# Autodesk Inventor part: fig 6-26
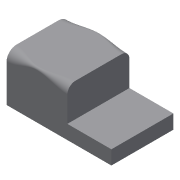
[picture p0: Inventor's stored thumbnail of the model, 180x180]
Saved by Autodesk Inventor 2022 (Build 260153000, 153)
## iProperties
Created: 2004-05
Part Number: fig 6-26
Document SubType Name: Modeling
Designer: CADCIM Technologies
Manufacturer: Standard
Standards Organization: Custom
Density: 1 g/cm^3
Material: Generic
Appearance: Default
Author: CADCIM Technologies
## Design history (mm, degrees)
node "Sketch1"
sketch "Sketch2"
  geometry: L1 (0.098, 47.711)-(0.098, 0.049); L2 (0.098, 0.049)-(-105.483, 0.049); L3 (-105.483, 0.049)-(-105.483, 14.192); L4 (-105.483, 14.192)-(-61.139, 14.192); L5 (-61.139, 14.192)-(-61.139, 47.711); L6 (-61.139, 47.711)-(0.098, 47.711)
  constraints: 12 end point, 3 parallel, 2 perpendicular, 1 vertical
extrude "Extrusion1" new body sketch "Sketch2" stored distance "d0" = 62.5; taper "d1" = 0 deg
fillet "Fillet9" dims "d61" = 10, "d62" = 8, "d63" = 2, "d64" = 5
fillet "Fillet10" dims "d65" = 8, "d66" = 10, "d67" = 2, "d68" = 5
body "Solid1"
